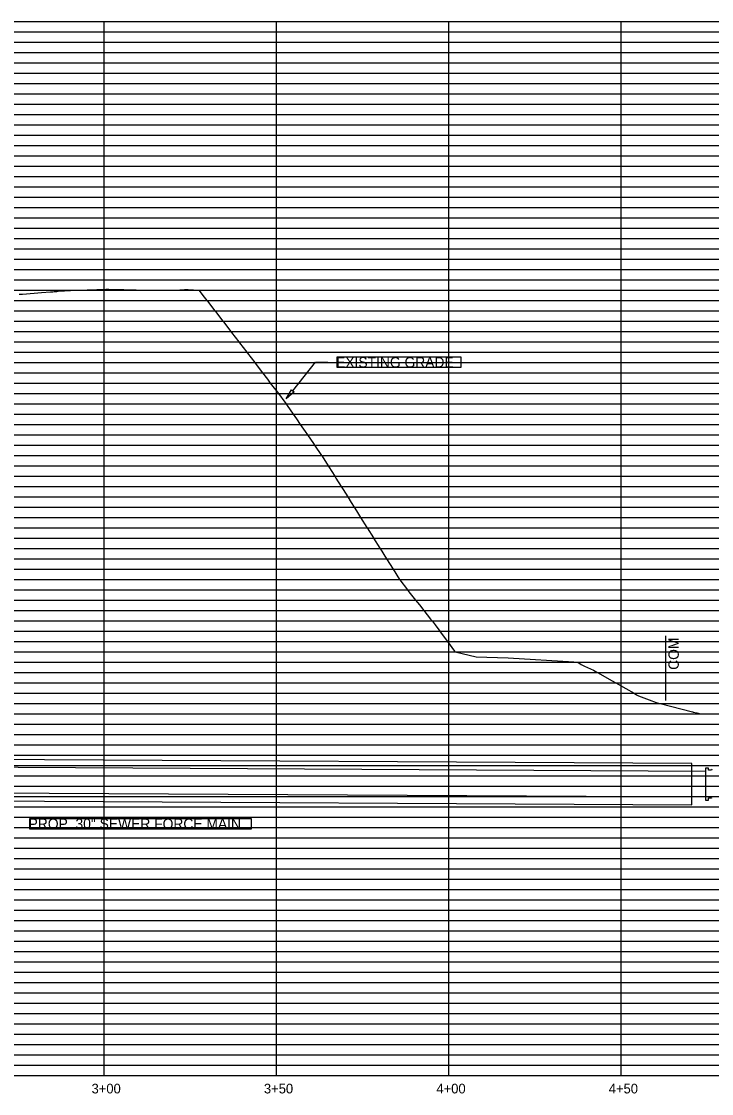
# Model space of a CAD drawing. Extents: x 1961446 to 1965364, y 798002 to 798458.
# Drawn here: x 1965028.3 to 1965228.5, y 798002.3 to 798313.5 of the extents above; entities that cross this region are included whole.
import ezdxf

# ---------------------------------------------------------------- set-up
doc = ezdxf.new("R2010")
doc.units = 0
for name, color, linetype in [('_C3D-PRSR-ANNO', 7, 'Continuous'), ('_C3D-PRSR-PIPE-NEW 30 FM', 7, 'Continuous'), ('C-ANNO-SUBT', 7, 'Continuous'), ('C-GRID-MEDI', 7, 'Continuous'), ('C-GRID-THIN', 7, 'Continuous'), ('C-PROF-EXST', 7, 'Continuous'), ('C-SSWR-FMAN-FTTG', 7, 'Continuous'), ('C-SSWR-FMAN-PIPE', 7, 'Continuous'), ('C-UTIL-FITT-ANNO', 7, 'Continuous')]:
    doc.layers.add(name, color=color, linetype=linetype)

msp = doc.modelspace()

# ---------------------------------------------------------------- linework, layer by layer
at = {"layer": '_C3D-PRSR-ANNO'}
msp.add_lwpolyline([(1965215.28, 798116.4), (1965215.28, 798135.14)], dxfattribs=at)
at = {"layer": '_C3D-PRSR-PIPE-NEW 30 FM'}
msp.add_lwpolyline([(1964812.85, 798088.45), (1965222.8, 798086.11), (1965222.8, 798098.11), (1964812.85, 798100.45)], close=True, dxfattribs=at)
at = {"layer": 'C-GRID-MEDI'}
for points in [[(1964702.28, 798313.48), (1965352.28, 798313.48)], [(1964752.28, 798313.48), (1965283.11, 798313.48)], [(1965052.28, 798007.48), (1965052.28, 798313.48)], [(1965102.28, 798007.48), (1965102.28, 798313.48)], [(1965152.28, 798007.48), (1965152.28, 798313.48)], [(1965202.28, 798007.48), (1965202.28, 798313.48)], [(1964752.28, 798283.48), (1965283.11, 798283.48)], [(1964752.28, 798253.48), (1965283.11, 798253.48)], [(1964752.28, 798223.48), (1965283.11, 798223.48)], [(1964752.28, 798193.48), (1965283.11, 798193.48)], [(1964752.28, 798163.48), (1965283.11, 798163.48)], [(1964752.28, 798133.48), (1965283.11, 798133.48)], [(1964752.28, 798103.48), (1965283.11, 798103.48)], [(1964752.28, 798073.48), (1965283.11, 798073.48)], [(1964752.28, 798043.48), (1965283.11, 798043.48)], [(1964752.28, 798013.48), (1965283.11, 798013.48)], [(1964702.28, 798007.48), (1965352.28, 798007.48)], [(1964752.28, 798007.48), (1965283.11, 798007.48)]]:
    msp.add_lwpolyline(points, dxfattribs=at)
at = {"layer": 'C-GRID-THIN'}
for points in [[(1964752.28, 798310.48), (1965283.11, 798310.48)], [(1964752.28, 798307.48), (1965283.11, 798307.48)], [(1964752.28, 798304.48), (1965283.11, 798304.48)], [(1964752.28, 798301.48), (1965283.11, 798301.48)], [(1964752.28, 798298.48), (1965283.11, 798298.48)], [(1964752.28, 798295.48), (1965283.11, 798295.48)], [(1964752.28, 798292.48), (1965283.11, 798292.48)], [(1964752.28, 798289.48), (1965283.11, 798289.48)], [(1964752.28, 798286.48), (1965283.11, 798286.48)], [(1964752.28, 798280.48), (1965283.11, 798280.48)], [(1964752.28, 798277.48), (1965283.11, 798277.48)], [(1964752.28, 798274.48), (1965283.11, 798274.48)], [(1964752.28, 798271.48), (1965283.11, 798271.48)], [(1964752.28, 798268.48), (1965283.11, 798268.48)], [(1964752.28, 798265.48), (1965283.11, 798265.48)], [(1964752.28, 798262.48), (1965283.11, 798262.48)], [(1964752.28, 798259.48), (1965283.11, 798259.48)], [(1964752.28, 798256.48), (1965283.11, 798256.48)], [(1964752.28, 798250.48), (1965283.11, 798250.48)], [(1964752.28, 798247.48), (1965283.11, 798247.48)], [(1964752.28, 798244.48), (1965283.11, 798244.48)], [(1964752.28, 798241.48), (1965283.11, 798241.48)], [(1964752.28, 798238.48), (1965283.11, 798238.48)], [(1964752.28, 798235.48), (1965283.11, 798235.48)], [(1964752.28, 798232.48), (1965283.11, 798232.48)], [(1964752.28, 798229.48), (1965283.11, 798229.48)], [(1964752.28, 798226.48), (1965283.11, 798226.48)], [(1964752.28, 798220.48), (1965283.11, 798220.48)], [(1964752.28, 798217.48), (1965283.11, 798217.48)], [(1964752.28, 798214.48), (1965283.11, 798214.48)], [(1964752.28, 798211.48), (1965283.11, 798211.48)], [(1964752.28, 798208.48), (1965283.11, 798208.48)], [(1964752.28, 798205.48), (1965283.11, 798205.48)], [(1964752.28, 798202.48), (1965283.11, 798202.48)], [(1964752.28, 798199.48), (1965283.11, 798199.48)], [(1964752.28, 798196.48), (1965283.11, 798196.48)], [(1964752.28, 798190.48), (1965283.11, 798190.48)], [(1964752.28, 798187.48), (1965283.11, 798187.48)], [(1964752.28, 798184.48), (1965283.11, 798184.48)], [(1964752.28, 798181.48), (1965283.11, 798181.48)], [(1964752.28, 798178.48), (1965283.11, 798178.48)], [(1964752.28, 798175.48), (1965283.11, 798175.48)], [(1964752.28, 798172.48), (1965283.11, 798172.48)], [(1964752.28, 798169.48), (1965283.11, 798169.48)], [(1964752.28, 798166.48), (1965283.11, 798166.48)], [(1964752.28, 798160.48), (1965283.11, 798160.48)], [(1964752.28, 798157.48), (1965283.11, 798157.48)], [(1964752.28, 798154.48), (1965283.11, 798154.48)], [(1964752.28, 798151.48), (1965283.11, 798151.48)], [(1964752.28, 798148.48), (1965283.11, 798148.48)], [(1964752.28, 798145.48), (1965283.11, 798145.48)], [(1964752.28, 798142.48), (1965283.11, 798142.48)], [(1964752.28, 798139.48), (1965283.11, 798139.48)], [(1964752.28, 798136.48), (1965283.11, 798136.48)], [(1964752.28, 798130.48), (1965283.11, 798130.48)], [(1964752.28, 798127.48), (1965283.11, 798127.48)], [(1964752.28, 798124.48), (1965283.11, 798124.48)], [(1964752.28, 798121.48), (1965283.11, 798121.48)], [(1964752.28, 798118.48), (1965283.11, 798118.48)], [(1964752.28, 798115.48), (1965283.11, 798115.48)], [(1964752.28, 798112.48), (1965283.11, 798112.48)], [(1964752.28, 798109.48), (1965283.11, 798109.48)], [(1964752.28, 798106.48), (1965283.11, 798106.48)], [(1964752.28, 798100.48), (1965283.11, 798100.48)], [(1964752.28, 798097.48), (1965283.11, 798097.48)], [(1964752.28, 798094.48), (1965283.11, 798094.48)], [(1964752.28, 798091.48), (1965283.11, 798091.48)], [(1964752.28, 798088.48), (1965283.11, 798088.48)], [(1964752.28, 798085.48), (1965283.11, 798085.48)], [(1964752.28, 798082.48), (1965283.11, 798082.48)], [(1964752.28, 798079.48), (1965283.11, 798079.48)], [(1964752.28, 798076.48), (1965283.11, 798076.48)], [(1964752.28, 798070.48), (1965283.11, 798070.48)], [(1964752.28, 798067.48), (1965283.11, 798067.48)], [(1964752.28, 798064.48), (1965283.11, 798064.48)], [(1964752.28, 798061.48), (1965283.11, 798061.48)], [(1964752.28, 798058.48), (1965283.11, 798058.48)], [(1964752.28, 798055.48), (1965283.11, 798055.48)], [(1964752.28, 798052.48), (1965283.11, 798052.48)], [(1964752.28, 798049.48), (1965283.11, 798049.48)], [(1964752.28, 798046.48), (1965283.11, 798046.48)], [(1964752.28, 798040.48), (1965283.11, 798040.48)], [(1964752.28, 798037.48), (1965283.11, 798037.48)], [(1964752.28, 798034.48), (1965283.11, 798034.48)], [(1964752.28, 798031.48), (1965283.11, 798031.48)], [(1964752.28, 798028.48), (1965283.11, 798028.48)], [(1964752.28, 798025.48), (1965283.11, 798025.48)], [(1964752.28, 798022.48), (1965283.11, 798022.48)], [(1964752.28, 798019.48), (1965283.11, 798019.48)], [(1964752.28, 798016.48), (1965283.11, 798016.48)], [(1964752.28, 798010.48), (1965283.11, 798010.48)]]:
    msp.add_lwpolyline(points, dxfattribs=at)
at = {"layer": 'C-PROF-EXST'}
for points in [[(1965027.62, 798234.28), (1965028.63, 798234.36)], [(1965028.63, 798234.36), (1965031.98, 798234.59)], [(1965031.98, 798234.59), (1965034.18, 798234.76)], [(1965034.18, 798234.76), (1965036.76, 798234.96)], [(1965036.76, 798234.96), (1965037.12, 798234.99)], [(1965037.12, 798234.99), (1965037.43, 798235.03)], [(1965037.43, 798235.03), (1965037.78, 798235.06)], [(1965037.78, 798235.06), (1965038.08, 798235.09)], [(1965038.08, 798235.09), (1965038.6, 798235.14)], [(1965038.6, 798235.14), (1965039, 798235.18)], [(1965039, 798235.18), (1965044.37, 798235.48)], [(1965044.37, 798235.48), (1965047.37, 798235.6)], [(1965047.37, 798235.6), (1965047.5, 798235.6)], [(1965047.5, 798235.6), (1965047.62, 798235.6)], [(1965047.62, 798235.6), (1965052.83, 798235.73)], [(1965052.83, 798235.73), (1965053.7, 798235.74)], [(1965053.7, 798235.74), (1965058.02, 798235.64)], [(1965058.02, 798235.64), (1965061.63, 798235.59)], [(1965061.63, 798235.59), (1965064.34, 798235.51)], [(1965064.34, 798235.51), (1965065.33, 798235.5)], [(1965065.33, 798235.5), (1965065.42, 798235.5)], [(1965065.42, 798235.5), (1965066.34, 798235.48)], [(1965066.34, 798235.48), (1965069.63, 798235.48)], [(1965069.63, 798235.48), (1965070.36, 798235.48)], [(1965070.36, 798235.48), (1965070.92, 798235.48)], [(1965070.92, 798235.48), (1965071.16, 798235.48)], [(1965071.16, 798235.48), (1965071.24, 798235.48)], [(1965071.24, 798235.48), (1965071.31, 798235.48)], [(1965071.31, 798235.48), (1965071.76, 798235.48)], [(1965071.76, 798235.48), (1965071.76, 798235.48)], [(1965071.76, 798235.48), (1965071.79, 798235.48)], [(1965071.79, 798235.48), (1965072.1, 798235.5)], [(1965071.79, 798235.48), (1965071.79, 798235.48)], [(1965072.1, 798235.5), (1965072.35, 798235.5)], [(1965072.35, 798235.5), (1965072.37, 798235.5)], [(1965072.37, 798235.5), (1965072.51, 798235.51)], [(1965072.51, 798235.51), (1965072.55, 798235.51)], [(1965072.55, 798235.51), (1965072.78, 798235.52)], [(1965072.78, 798235.52), (1965075.64, 798235.65)], [(1965075.64, 798235.65), (1965076.71, 798235.64)], [(1965076.71, 798235.64), (1965079.8, 798235.48)], [(1965079.8, 798235.48), (1965081.36, 798233.45)], [(1965081.36, 798233.45), (1965082.11, 798232.48)], [(1965082.11, 798232.48), (1965082.27, 798232.28)], [(1965082.27, 798232.28), (1965084.43, 798229.48)], [(1965084.43, 798229.48), (1965084.59, 798229.27)], [(1965084.59, 798229.27), (1965086.74, 798226.48)], [(1965086.74, 798226.48), (1965086.92, 798226.25)], [(1965086.92, 798226.25), (1965089.05, 798223.48)], [(1965089.05, 798223.48), (1965089.25, 798223.23)], [(1965089.25, 798223.23), (1965091.36, 798220.48)], [(1965091.36, 798220.48), (1965091.58, 798220.2)], [(1965091.58, 798220.2), (1965093.68, 798217.48)], [(1965093.68, 798217.48), (1965093.93, 798217.15)], [(1965093.93, 798217.15), (1965095.99, 798214.48)], [(1965095.99, 798214.48), (1965096.41, 798213.93)], [(1965096.41, 798213.93), (1965098.22, 798211.48)], [(1965098.22, 798211.48), (1965099.7, 798209.6)], [(1965099.7, 798209.6), (1965100.49, 798208.48)], [(1965100.49, 798208.48), (1965102.9, 798205.51)], [(1965102.9, 798205.51), (1965102.92, 798205.48)], [(1965102.92, 798205.48), (1965104.78, 798202.98)], [(1965104.78, 798202.98), (1965105.11, 798202.48)], [(1965105.11, 798202.48), (1965105.46, 798201.98)], [(1965105.46, 798201.98), (1965107.16, 798199.48)], [(1965107.16, 798199.48), (1965108.1, 798198.12)], [(1965108.1, 798198.12), (1965109.22, 798196.48)], [(1965109.22, 798196.48), (1965110.61, 798194.46)], [(1965110.61, 798194.46), (1965111.28, 798193.48)], [(1965111.28, 798193.48), (1965113.04, 798190.93)], [(1965113.04, 798190.93), (1965113.35, 798190.48)], [(1965113.35, 798190.48), (1965115.41, 798187.5)], [(1965115.41, 798187.5), (1965115.42, 798187.48)], [(1965115.42, 798187.48), (1965115.54, 798187.32)], [(1965115.54, 798187.32), (1965117.32, 798184.48)], [(1965117.32, 798184.48), (1965117.52, 798184.17)], [(1965117.52, 798184.17), (1965119.21, 798181.48)], [(1965119.21, 798181.48), (1965119.58, 798180.89)], [(1965119.58, 798180.89), (1965121.09, 798178.48)], [(1965121.09, 798178.48), (1965121.65, 798177.59)], [(1965121.65, 798177.59), (1965122.98, 798175.48)], [(1965122.98, 798175.48), (1965123.99, 798173.85)], [(1965123.99, 798173.85), (1965124.85, 798172.48)], [(1965124.85, 798172.48), (1965125.52, 798171.41)], [(1965125.52, 798171.41), (1965126.73, 798169.48)], [(1965126.73, 798169.48), (1965128.53, 798166.62)], [(1965128.53, 798166.62), (1965128.61, 798166.48)], [(1965128.61, 798166.48), (1965130.44, 798163.58)], [(1965130.44, 798163.58), (1965130.5, 798163.48)], [(1965130.5, 798163.48), (1965132.34, 798160.55)], [(1965132.34, 798160.55), (1965132.38, 798160.48)], [(1965132.38, 798160.48), (1965134.24, 798157.53)], [(1965134.24, 798157.53), (1965134.26, 798157.48)], [(1965134.26, 798157.48), (1965136.13, 798154.51)], [(1965136.13, 798154.51), (1965136.15, 798154.48)], [(1965136.15, 798154.48), (1965138.03, 798151.49)], [(1965138.03, 798151.49), (1965138.03, 798151.48)], [(1965138.03, 798151.48), (1965138.04, 798151.48)], [(1965138.04, 798151.48), (1965138.12, 798151.37)], [(1965138.12, 798151.37), (1965140.3, 798148.48)], [(1965140.3, 798148.48), (1965140.73, 798147.94)], [(1965140.73, 798147.94), (1965142.67, 798145.48)], [(1965142.67, 798145.48), (1965143.77, 798144.1)], [(1965143.77, 798144.1), (1965145.05, 798142.48)], [(1965145.05, 798142.48), (1965147.03, 798140)], [(1965147.03, 798140), (1965147.44, 798139.48)], [(1965147.44, 798139.48), (1965148.34, 798138.34)], [(1965148.34, 798138.34), (1965149.72, 798136.48)], [(1965149.72, 798136.48), (1965150.13, 798135.93)], [(1965150.13, 798135.93), (1965151.95, 798133.48)], [(1965151.95, 798133.48), (1965153.99, 798130.73)], [(1965153.99, 798130.73), (1965154.18, 798130.48)], [(1965154.18, 798130.48), (1965160.24, 798129.06)], [(1965160.24, 798129.06), (1965169.49, 798128.79)], [(1965169.49, 798128.79), (1965188.59, 798127.56)], [(1965188.59, 798127.56), (1965188.95, 798127.53)], [(1965188.95, 798127.53), (1965189.16, 798127.53)], [(1965189.16, 798127.53), (1965189.71, 798127.48)], [(1965189.71, 798127.48), (1965190.71, 798126.82)], [(1965190.71, 798126.82), (1965191.69, 798126.36)], [(1965191.69, 798126.36), (1965194.28, 798125.16)], [(1965194.28, 798125.16), (1965195.3, 798124.58)], [(1965195.3, 798124.58), (1965195.47, 798124.48)], [(1965195.47, 798124.48), (1965199.69, 798122.09)], [(1965199.69, 798122.09), (1965200.76, 798121.48)], [(1965200.76, 798121.48), (1965203.65, 798119.84)], [(1965203.65, 798119.84), (1965206.05, 798118.48)], [(1965206.05, 798118.48), (1965206.8, 798118.06)], [(1965206.8, 798118.06), (1965207.36, 798117.74)], [(1965207.36, 798117.74), (1965210.39, 798116.58)], [(1965210.39, 798116.58), (1965212.49, 798115.79)], [(1965212.49, 798115.79), (1965213.67, 798115.48)], [(1965213.67, 798115.48), (1965222.96, 798113.1)], [(1965222.96, 798113.1), (1965223.11, 798113.04)], [(1965223.11, 798113.04), (1965223.23, 798112.99)], [(1965223.23, 798112.99), (1965224.24, 798112.75)], [(1965224.24, 798112.75), (1965225.32, 798112.48)], [(1965225.32, 798112.48), (1965225.33, 798112.48)], [(1965225.33, 798112.48), (1965225.41, 798112.48)], [(1965225.41, 798112.48), (1965228.48, 798112.47)], [(1965228.48, 798112.47), (1965230.55, 798112.47)]]:
    msp.add_lwpolyline(points, dxfattribs=at)
at = {"layer": 'C-SSWR-FMAN-FTTG'}
for points in [[(1965227.69, 798096.76), (1965226.74, 798096.76)], [(1965226.74, 798096.76), (1965226.74, 798096.5)], [(1965226.74, 798096.5), (1965226.74, 798087.72)], [(1965227.69, 798096.12), (1965227.69, 798096.76)], [(1965228.49, 798096.12), (1965227.69, 798096.12)], [(1965228.63, 798096.42), (1965228.49, 798096.12)], [(1965227.69, 798087.46), (1965227.69, 798088.1)], [(1965227.69, 798088.1), (1965228.49, 798088.1)], [(1965228.49, 798088.1), (1965228.53, 798087.98)], [(1965226.74, 798087.72), (1965226.74, 798087.46)], [(1965226.74, 798087.46), (1965227.69, 798087.46)]]:
    msp.add_lwpolyline(points, dxfattribs=at)
at = {"layer": 'C-SSWR-FMAN-PIPE'}
for points in [[(1964811.35, 798098.23), (1965226.74, 798095.86)], [(1964811.35, 798090.73), (1965226.74, 798088.36)]]:
    msp.add_lwpolyline(points, dxfattribs=at)
at = {"layer": 'C-UTIL-FITT-ANNO'}
for points in [[(1965119.94, 798216.09), (1965155.81, 798216.09), (1965155.81, 798212.99), (1965119.94, 798212.99)], [(1965107.41, 798205.92), (1965105.15, 798203.89), (1965106.63, 798206.54)], [(1965030.74, 798082.13), (1965095.02, 798082.13), (1965095.02, 798079.02), (1965030.74, 798079.02)]]:
    msp.add_lwpolyline(points, close=True, dxfattribs=at)
for points in [[(1965107.02, 798206.23), (1965113.66, 798214.57)], [(1965113.66, 798214.57), (1965117.24, 798214.57)]]:
    msp.add_lwpolyline(points, dxfattribs=at)

# ---------------------------------------------------------------- texts
at = {"layer": 'C-ANNO-SUBT'}
for s, p in [('3+00', (1965048.67, 798002.31)), ('3+50', (1965098.67, 798002.31)), ('4+00', (1965148.71, 798002.31)), ('4+50', (1965198.71, 798002.31))]:
    msp.add_text(s, height=2.814, rotation=360, dxfattribs=at).set_placement(p)
at = {"layer": 'C-UTIL-FITT-ANNO'}
for s, p in [('EXISTING GRADE', (1965119.61, 798213.04)), ('PROP. 30" SEWER FORCE MAIN', (1965030.41, 798079.08))]:
    msp.add_text(s, height=3, dxfattribs=at).set_placement(p)
msp.add_text('COM', height=3, rotation=90, dxfattribs=at).set_placement((1965219.03, 798125.27))

doc.saveas('drawing.dxf')
